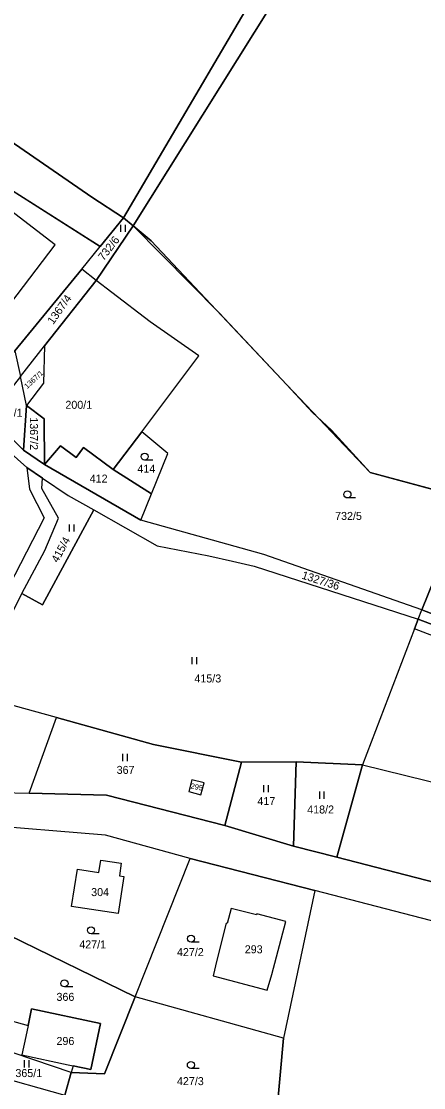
# Model space of a CAD drawing. Extents: x -588699 to -585793, y -1060280 to -1056731.
# Drawn here: x -587215.1 to -587129.7, y -1058613.5 to -1058386.9 of the extents above; entities that cross this region are included whole.
import ezdxf

# ---------------------------------------------------------------- set-up
doc = ezdxf.new("R2010")
doc.units = 0
for name, color, linetype in [('Druh pozemku', 7, 'Continuous'), ('Lesy', 7, 'Continuous'), ('Parcela nároku', 7, 'Continuous')]:
    doc.layers.add(name, color=color, linetype=linetype)

msp = doc.modelspace()

# ---------------------------------------------------------------- linework, layer by layer
at = {"layer": 'Druh pozemku'}
for p, q in [((-587194.04, -1058430.15), (-587194.04, -1058431.65)), ((-587193.02, -1058431.65), (-587193.02, -1058430.15)), ((-587187.19, -1058480.14), (-587188.94, -1058480.14)), ((-587144.15, -1058488.18), (-587145.9, -1058488.18)), ((-587204.95, -1058493.78), (-587204.95, -1058495.28)), ((-587203.93, -1058495.28), (-587203.93, -1058493.78)), ((-587178.89, -1058521.99), (-587178.89, -1058523.49)), ((-587177.86, -1058523.49), (-587177.86, -1058521.99)), ((-587193.61, -1058542.56), (-587193.61, -1058544.06)), ((-587192.58, -1058544.06), (-587192.58, -1058542.56)), ((-587163.69, -1058549.16), (-587163.69, -1058550.66)), ((-587162.67, -1058550.66), (-587162.67, -1058549.16)), ((-587151.84, -1058550.57), (-587151.84, -1058552.07)), ((-587150.82, -1058552.07), (-587150.82, -1058550.57)), ((-587198.57, -1058580.77), (-587200.32, -1058580.77)), ((-587177.34, -1058582.55), (-587179.09, -1058582.55)), ((-587204.2, -1058592.06), (-587205.95, -1058592.06)), ((-587214.48, -1058607.65), (-587214.48, -1058609.15)), ((-587213.45, -1058609.15), (-587213.45, -1058607.65)), ((-587177.37, -1058609.39), (-587179.12, -1058609.39))]:
    msp.add_line(p, q, dxfattribs=at)
for centre in [(-587188.94, -1058479.39), (-587145.9, -1058487.43), (-587200.32, -1058580.02), (-587179.09, -1058581.8), (-587205.95, -1058591.31), (-587179.12, -1058608.64)]:
    msp.add_circle(centre, 0.75, dxfattribs=at)
at = {"layer": 'Lesy'}
for p, q in [((-587224.75, -1058418), (-587198.38, -1058434.72)), ((-587198.38, -1058434.72), (-587193.45, -1058428.69)), ((-587193.45, -1058428.69), (-587191.39, -1058430.39)), ((-587191.39, -1058430.39), (-587173.13, -1058448.86)), ((-587173.13, -1058448.86), (-587158.73, -1058464.14)), ((-587158.73, -1058464.14), (-587141.1, -1058482.75)), ((-587141.1, -1058482.75), (-587120.59, -1058488.29))]:
    msp.add_line(p, q, dxfattribs=at)
at = {"layer": 'Parcela nároku'}
for points in [[(-587093.47, -1058042.85), (-587083.2, -1058085.63), (-587087.45, -1058131.23), (-587096.95, -1058176.54), (-587108.49, -1058212.36), (-587125.77, -1058278.15), (-587153.1, -1058357.53), (-587158, -1058368.22), (-587193.45, -1058428.69), (-587200.12, -1058424.25), (-587247.18, -1058391.8), (-587222.83, -1058325.23), (-587191.01, -1058241.74), (-587172.24, -1058142), (-587169.7, -1058107.61), (-587162.67, -1058067.38), (-587154.26, -1057976.54), (-587133.01, -1057983.57), (-587113.33, -1057983.29)], [(-587108.49, -1058212.36), (-587096.95, -1058176.54), (-587087.45, -1058131.23), (-587083.2, -1058085.63), (-587093.47, -1058042.85), (-587113.33, -1057983.29), (-587108.57, -1057984.69), (-587093.66, -1058027.53), (-587078.98, -1058086.47), (-587083.52, -1058130.86), (-587092.03, -1058176.89), (-587104.48, -1058214.01), (-587120.31, -1058276.98), (-587148.32, -1058357.26), (-587158.27, -1058377.37), (-587191.39, -1058430.39), (-587193.45, -1058428.69), (-587158, -1058368.22), (-587153.1, -1058357.53), (-587125.77, -1058278.15)], [(-587200.12, -1058424.25), (-587193.45, -1058428.69), (-587198.38, -1058434.72), (-587251.12, -1058401.27), (-587247.18, -1058391.8)], [(-587251.12, -1058401.27), (-587265.77, -1058425.67), (-587258.32, -1058429.81), (-587255.52, -1058438.13), (-587258.81, -1058443.53), (-587225.6, -1058468.06), (-587216.48, -1058456.91), (-587202.3, -1058439.56), (-587198.38, -1058434.72)], [(-587207.96, -1058434.4), (-587234.94, -1058413.66), (-587244.39, -1058426.04), (-587217.34, -1058446.81)], [(-587244.39, -1058426.04), (-587217.34, -1058446.81), (-587207.96, -1058434.4), (-587234.94, -1058413.66)], [(-587198.38, -1058434.72), (-587193.45, -1058428.69), (-587191.39, -1058430.39), (-587199.2, -1058441.97), (-587202.3, -1058439.56)], [(-587187.53, -1058433.57), (-587158.73, -1058464.14), (-587153.29, -1058470.04), (-587149.3, -1058473.77), (-587141.1, -1058482.75), (-587120.59, -1058488.29), (-587130.11, -1058511.95), (-587163.61, -1058500.22), (-587189.74, -1058492.88), (-587187.46, -1058487.29), (-587183.98, -1058478.73), (-587189.54, -1058474.15), (-587177.45, -1058457.99), (-587187.78, -1058450.77), (-587195.93, -1058444.52), (-587199.2, -1058441.97), (-587191.39, -1058430.39)], [(-587199.2, -1058441.97), (-587202.3, -1058439.56), (-587216.48, -1058456.91), (-587215.32, -1058462.4), (-587210.18, -1058455.88)], [(-587187.78, -1058450.77), (-587195.93, -1058444.52), (-587199.2, -1058441.97), (-587210.18, -1058455.88), (-587210.39, -1058463.77), (-587214.03, -1058468.54), (-587210.28, -1058471.33), (-587210.2, -1058481.04), (-587206.79, -1058477.09), (-587203.46, -1058479.56), (-587201.93, -1058477.48), (-587195.65, -1058482.14), (-587189.54, -1058474.15), (-587177.45, -1058457.99)], [(-587215.32, -1058462.4), (-587210.18, -1058455.88), (-587210.39, -1058463.77), (-587214.03, -1058468.54)], [(-587213.4, -1058486.33), (-587210.26, -1058492.43), (-587217.76, -1058506.98), (-587219.41, -1058506.08), (-587241.65, -1058493.95), (-587258.72, -1058484.38), (-587259.1, -1058484.17), (-587254.23, -1058475.11), (-587244.04, -1058457.89), (-587232.65, -1058465.52), (-587227.16, -1058469.96), (-587213.95, -1058481.71)], [(-587215.32, -1058462.4), (-587221.93, -1058470.77), (-587214.67, -1058478.01), (-587214.03, -1058468.54)], [(-587225.6, -1058468.06), (-587227.16, -1058469.96), (-587213.95, -1058481.71), (-587210.64, -1058483.94), (-587205.14, -1058487.64), (-587199.74, -1058490.68), (-587186.25, -1058498.36), (-587175.33, -1058500.5), (-587170.32, -1058501.58), (-587165.67, -1058502.67), (-587130.85, -1058513.89), (-587130.11, -1058511.95), (-587163.61, -1058500.22), (-587189.74, -1058492.88), (-587210.2, -1058481.04), (-587214.67, -1058478.01), (-587221.93, -1058470.77)], [(-587210.28, -1058471.33), (-587214.03, -1058468.54), (-587214.67, -1058478.01), (-587210.2, -1058481.04)], [(-587183.98, -1058478.73), (-587189.54, -1058474.15), (-587195.65, -1058482.14), (-587187.46, -1058487.29)], [(-587203.46, -1058479.56), (-587206.79, -1058477.09), (-587210.2, -1058481.04), (-587189.74, -1058492.88), (-587187.46, -1058487.29), (-587195.65, -1058482.14), (-587201.93, -1058477.48)], [(-587234.29, -1058538.66), (-587236.02, -1058541.4), (-587237.26, -1058543.38), (-587233.82, -1058545.1), (-587225.72, -1058529.88), (-587215.02, -1058508.46), (-587210.13, -1058499.35), (-587207.22, -1058492.46), (-587210.78, -1058486.13), (-587210.64, -1058483.94), (-587213.95, -1058481.71), (-587213.4, -1058486.33), (-587210.26, -1058492.43), (-587217.76, -1058506.98), (-587224.43, -1058519.56)], [(-587210.13, -1058499.35), (-587207.22, -1058492.46), (-587210.78, -1058486.13), (-587210.64, -1058483.94), (-587205.14, -1058487.64), (-587199.74, -1058490.68), (-587210.64, -1058510.86), (-587215.02, -1058508.46)], [(-587120.59, -1058488.29), (-587107.81, -1058492.23), (-587068.93, -1058497.09), (-587078.81, -1058527.57), (-587080.08, -1058527.48), (-587104.59, -1058521.82), (-587130.11, -1058511.95)], [(-587215.02, -1058508.46), (-587210.64, -1058510.86), (-587199.74, -1058490.68), (-587186.25, -1058498.36), (-587175.33, -1058500.5), (-587170.32, -1058501.58), (-587165.67, -1058502.67), (-587130.85, -1058513.89), (-587131.64, -1058515.97), (-587142.7, -1058544.9), (-587156.77, -1058544.27), (-587168.4, -1058544.32), (-587187.04, -1058540.53), (-587207.62, -1058534.79), (-587225.72, -1058529.88)], [(-587131.64, -1058515.97), (-587130.85, -1058513.89), (-587106.45, -1058523.25), (-587081.17, -1058529.23), (-587067.44, -1058530.49), (-587069.45, -1058533.67), (-587089.18, -1058529.55), (-587104.92, -1058526.27)], [(-587130.85, -1058513.89), (-587130.11, -1058511.95), (-587104.59, -1058521.82), (-587080.08, -1058527.48), (-587078.81, -1058527.57), (-587066.52, -1058528.46), (-587060.81, -1058526.91), (-587050.75, -1058527.22), (-587043.8, -1058526.3), (-587036.17, -1058523.73), (-587036.25, -1058527.75), (-587041.6, -1058529.5), (-587044.77, -1058530.53), (-587067.44, -1058530.49), (-587081.17, -1058529.23), (-587106.45, -1058523.25)], [(-587104.92, -1058526.27), (-587131.64, -1058515.97), (-587142.7, -1058544.9), (-587097.55, -1058555.98), (-587089.18, -1058529.55)], [(-587207.62, -1058534.79), (-587225.72, -1058529.88), (-587233.82, -1058545.1), (-587219.46, -1058550.78), (-587213.45, -1058550.88)], [(-587187.04, -1058540.53), (-587168.4, -1058544.32), (-587171.91, -1058557.78), (-587197.03, -1058551.33), (-587213.45, -1058550.88), (-587207.62, -1058534.79)], [(-587168.4, -1058544.32), (-587156.77, -1058544.27), (-587157.35, -1058562.14), (-587171.91, -1058557.78)], [(-587157.35, -1058562.14), (-587156.77, -1058544.27), (-587142.7, -1058544.9), (-587148.16, -1058564.51)], [(-587148.16, -1058564.51), (-587142.7, -1058544.9), (-587097.55, -1058555.98), (-587083, -1058560.66), (-587047.58, -1058559.53), (-587047.89, -1058564.7), (-587046, -1058572.34), (-587055.26, -1058575.46), (-587107.59, -1058563.12), (-587110.09, -1058575.51), (-587116.69, -1058572.64)], [(-587177.01, -1058551.23), (-587176.33, -1058548.68), (-587178.9, -1058548.03), (-587179.56, -1058550.57)], [(-587176.33, -1058548.68), (-587178.9, -1058548.03), (-587179.56, -1058550.57), (-587177.01, -1058551.23)], [(-587179.24, -1058564.76), (-587197.27, -1058559.81), (-587224.85, -1058557.57), (-587219.33, -1058566.05), (-587217.74, -1058574.1), (-587217.93, -1058581), (-587190.97, -1058594.14)], [(-587193.32, -1058568.57), (-587194.54, -1058576.46), (-587204.43, -1058574.94), (-587203.17, -1058567.04), (-587198.67, -1058567.75), (-587198.25, -1058565.11), (-587193.9, -1058565.77), (-587194.3, -1058568.42)], [(-587203.17, -1058567.04), (-587198.67, -1058567.75), (-587198.25, -1058565.11), (-587193.9, -1058565.77), (-587194.3, -1058568.42), (-587193.32, -1058568.57), (-587194.54, -1058576.46), (-587204.43, -1058574.94)], [(-587179.24, -1058564.76), (-587152.84, -1058571.54), (-587159.45, -1058602.92), (-587190.97, -1058594.14)], [(-587174.41, -1058589.73), (-587162.91, -1058592.77), (-587161.95, -1058589.4), (-587159, -1058578.14), (-587165.13, -1058576.56), (-587165.18, -1058576.75), (-587170.59, -1058575.38), (-587171.42, -1058578.58), (-587171.61, -1058578.53), (-587173.65, -1058586.34)], [(-587165.13, -1058576.56), (-587165.18, -1058576.75), (-587170.59, -1058575.38), (-587171.42, -1058578.58), (-587171.61, -1058578.53), (-587173.65, -1058586.34), (-587174.41, -1058589.73), (-587162.91, -1058592.77), (-587161.95, -1058589.4), (-587159, -1058578.14)], [(-587217.93, -1058581), (-587218.3, -1058584.32), (-587219.27, -1058598.66), (-587213.68, -1058600.22), (-587212.93, -1058596.7), (-587198.3, -1058599.82), (-587200.38, -1058609.6), (-587204.14, -1058608.8), (-587204.54, -1058610.23), (-587197.46, -1058610.49), (-587190.97, -1058594.14)], [(-587190.97, -1058594.14), (-587197.46, -1058610.49), (-587204.54, -1058610.23), (-587205.89, -1058615.04), (-587161.65, -1058627.33), (-587159.45, -1058602.92)], [(-587213.68, -1058600.22), (-587214.17, -1058602.56), (-587215.01, -1058606.5), (-587205.19, -1058608.58), (-587204.14, -1058608.8), (-587200.38, -1058609.6), (-587198.3, -1058599.82), (-587212.93, -1058596.7)], [(-587219.27, -1058598.66), (-587213.68, -1058600.22), (-587214.17, -1058602.56), (-587215.01, -1058606.5), (-587205.19, -1058608.58), (-587204.14, -1058608.8), (-587204.54, -1058610.23), (-587220.69, -1058604.79)], [(-587204.54, -1058610.23), (-587220.69, -1058604.79), (-587222.03, -1058610.55), (-587205.89, -1058615.04)], [(-587205.89, -1058615.04), (-587161.65, -1058627.33), (-587163.66, -1058639.96), (-587194.34, -1058630.79), (-587194.82, -1058632.21), (-587225.61, -1058623.88), (-587222.03, -1058610.55)]]:
    msp.add_lwpolyline(points, close=True, dxfattribs=at)
for points in [[(-587120.59, -1058488.29), (-587141.1, -1058482.75), (-587149.3, -1058473.77), (-587153.29, -1058470.04), (-587158.73, -1058464.14), (-587187.53, -1058433.57), (-587191.39, -1058430.39), (-587158.27, -1058377.37), (-587148.32, -1058357.26), (-587120.31, -1058276.98)], [(-587219.46, -1058550.78), (-587213.45, -1058550.88), (-587197.03, -1058551.33), (-587171.91, -1058557.78), (-587157.35, -1058562.14), (-587148.16, -1058564.51), (-587116.69, -1058572.64)], [(-587117.07, -1058580.86), (-587152.84, -1058571.54), (-587179.24, -1058564.76), (-587197.27, -1058559.81), (-587224.85, -1058557.57)], [(-587117.07, -1058580.86), (-587152.84, -1058571.54), (-587159.45, -1058602.92), (-587161.65, -1058627.33), (-587140.01, -1058634.05), (-587129.38, -1058630.44)]]:
    msp.add_lwpolyline(points, dxfattribs=at)

# ---------------------------------------------------------------- texts
for s, height, rotation, p in [('732/6', 1.7, 52.079, (-587197.65, -1058437.88)), ('1367/4', 1.7, 54.8231, (-587208.34, -1058451.44)), ('1367/1', 1.14, 42.5181, (-587213.87, -1058465.05)), ('1367/2', 1.7, 270.1581, (-587213.29, -1058471.04)), ('415/4', 1.7, 61.6248, (-587207.36, -1058502.06)), ('1327/36', 1.7, 342.1396, (-587155.73, -1058505.27)), ('295', 1.14, 349.6721, (-587179.26, -1058549.89))]:
    msp.add_text(s, height=height, rotation=rotation, dxfattribs=at).set_placement(p)
for s, p in [('200/1', (-587205.76, -1058469.23)), ('735/1', (-587220.53, -1058470.91)), ('414', (-587190.47, -1058482.8)), ('412', (-587200.6, -1058484.91)), ('732/5', (-587148.51, -1058492.84)), ('415/3', (-587178.37, -1058527.37)), ('367', (-587194.88, -1058546.8)), ('417', (-587165, -1058553.41)), ('418/2', (-587154.43, -1058555.21)), ('304', (-587200.29, -1058572.76)), ('427/1', (-587202.81, -1058583.88)), ('427/2', (-587182.08, -1058585.51)), ('293', (-587167.69, -1058584.91)), ('366', (-587207.65, -1058595.02)), ('296', (-587207.65, -1058604.4)), ('365/1', (-587216.37, -1058611.21)), ('427/3', (-587182.08, -1058612.92))]:
    msp.add_text(s, height=1.7, dxfattribs=at).set_placement(p)

doc.saveas('drawing.dxf')
